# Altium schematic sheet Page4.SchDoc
size 431 x 279 mm; Date: Not shown in title block; ApprovedBy: Not shown in title block; CheckedBy: Not shown in title block; Author: Not shown in title block; CompanyName: Not shown in title block; Engineer: Not shown in title block; Organization: Not shown in title block; Address1: Not shown in title block; Address2: Not shown in title block; Address3: Not shown in title block; Address4: Not shown in title block; DocumentNumber: 5; Revision: Use project parameter SCH_Rev; SheetNumber: 5; SheetTotal: 5; PageSetup: Record=PageOptions|CenterHorizontal=True|CenterVertical=True|PrintScale=1.00|XCorrection=1.00|YCorrection=1.00|PrintKind=0|BorderSize=5000000|LeftOffset=0|BottomOffset=0|Orientation=2|PaperLength=1000|PaperWidth=1000|Scale=100|PaperSource=15|PrintQuality=600|MediaType=1|DitherType=10|PaperKind=Letter|PrintScaleMode=1
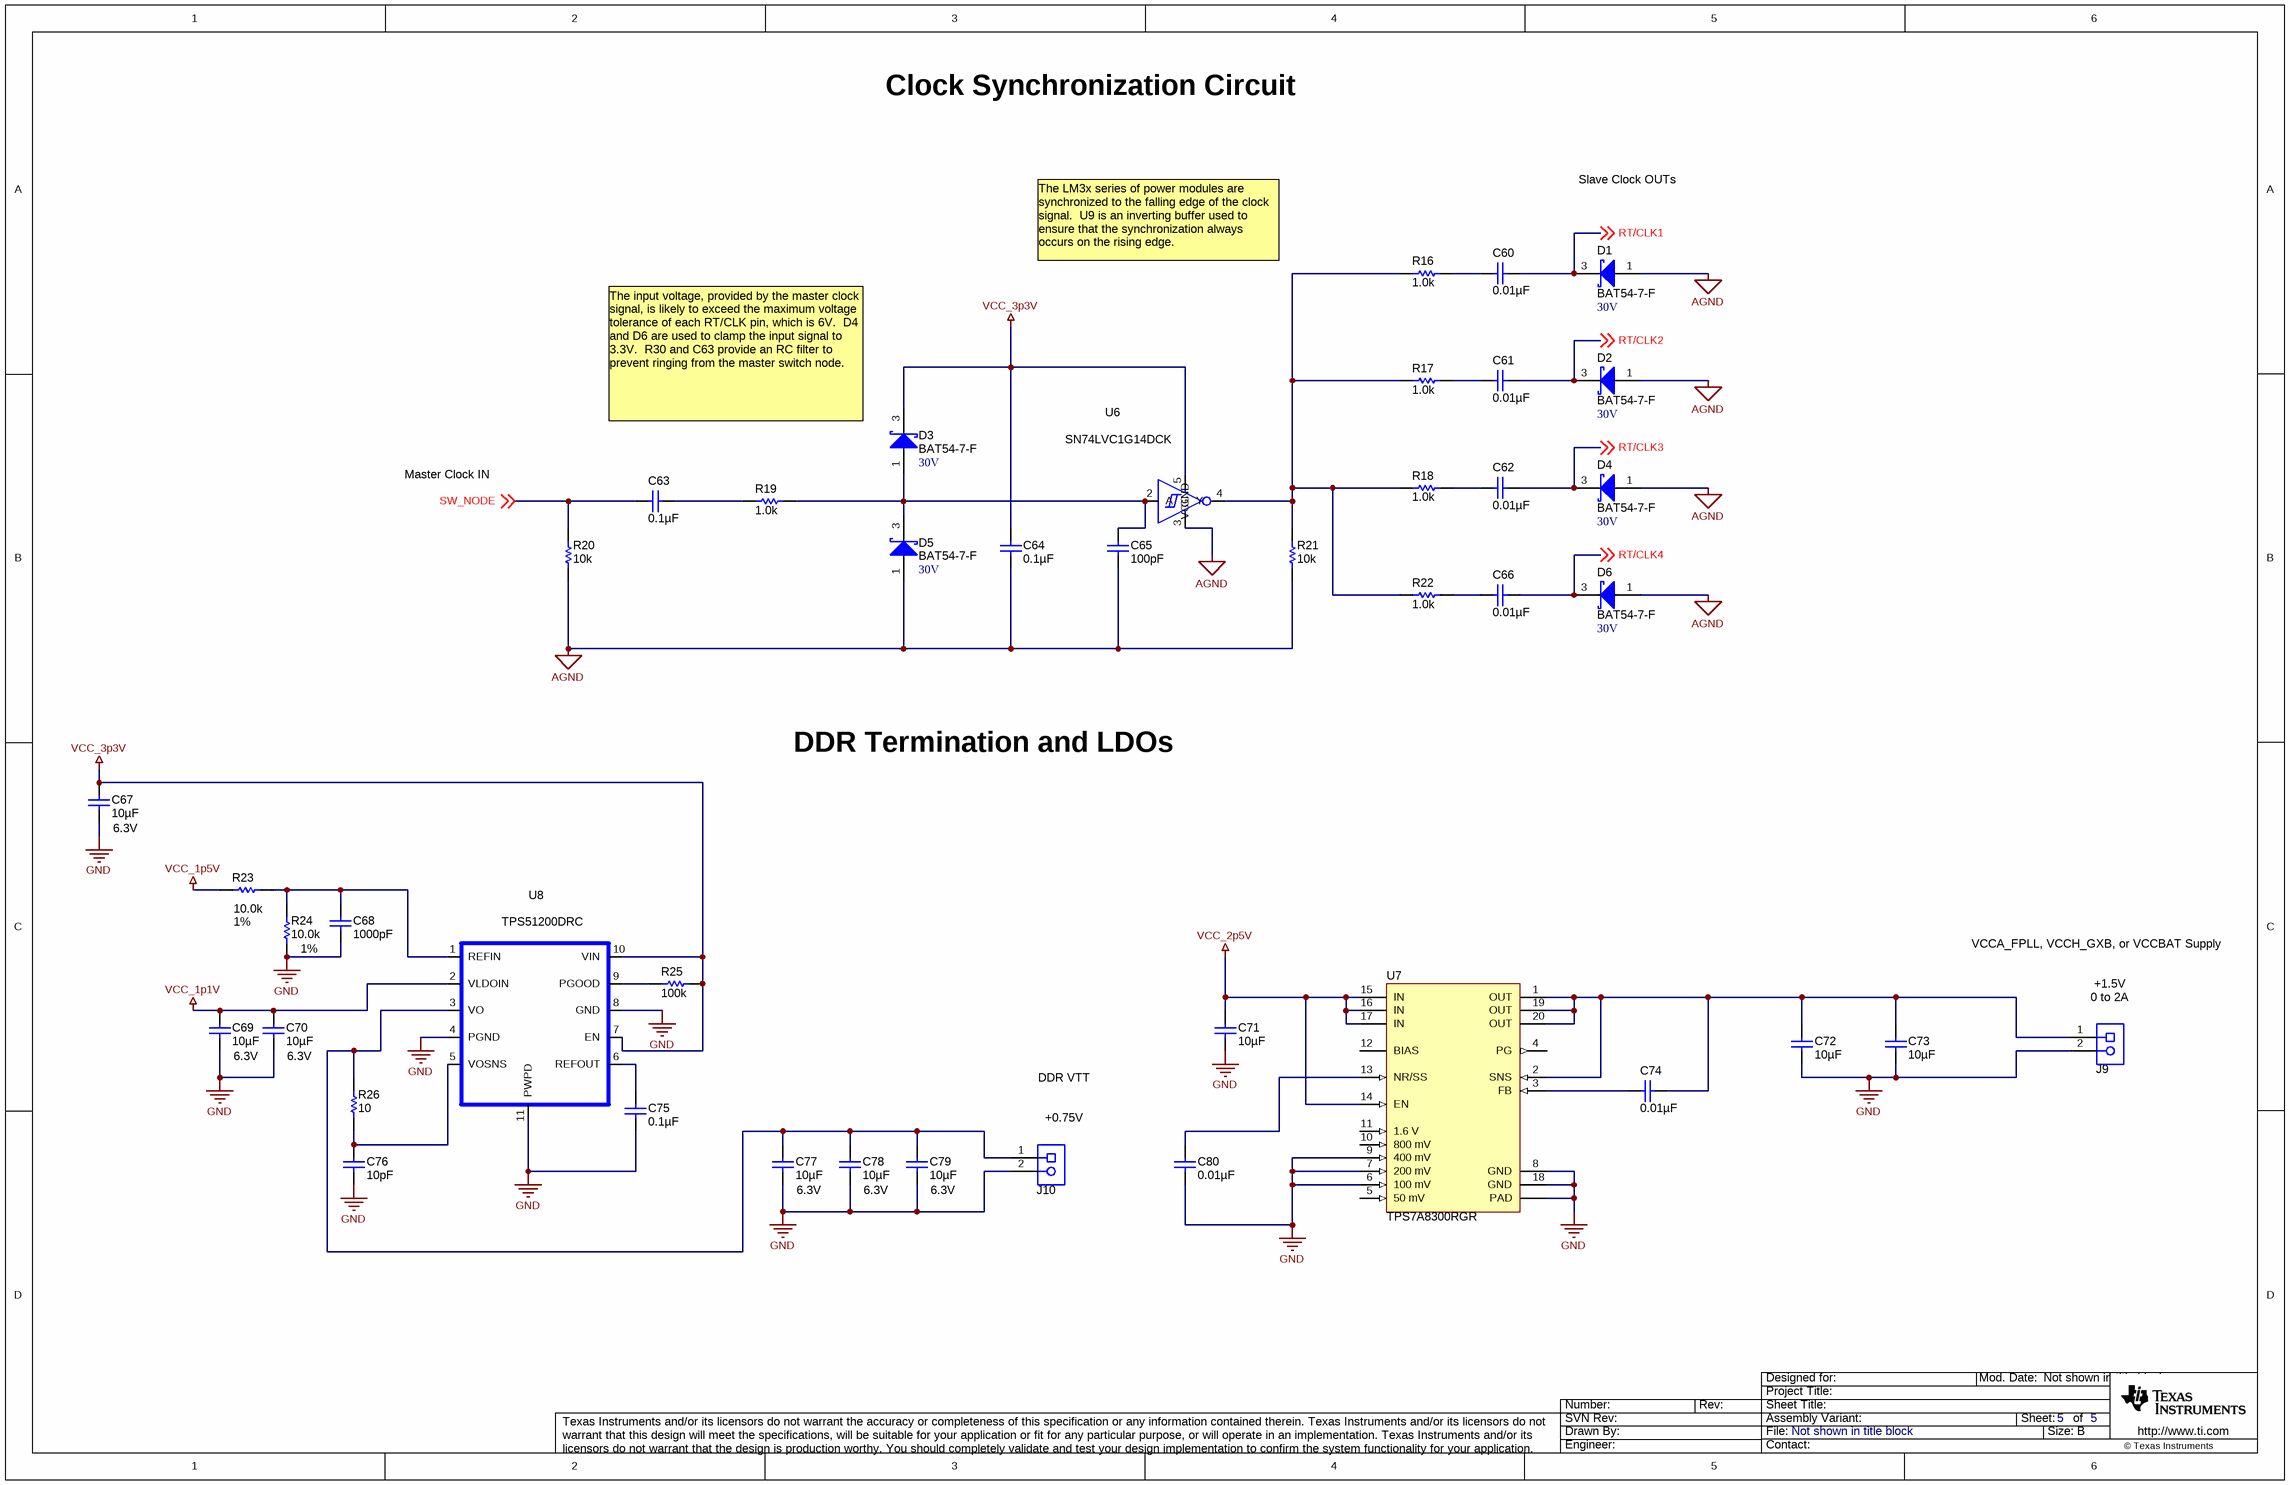
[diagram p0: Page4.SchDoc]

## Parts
C60  ValueDisplayed: 0.01µF  [0603]  (hidden comment: C0603C103J5RACTU)
C61  ValueDisplayed: 0.01µF  [0603]  (hidden comment: C0603C103J5RACTU)
C62  ValueDisplayed: 0.01µF  [0603]  (hidden comment: C0603C103J5RACTU)
C63  ValueDisplayed: 0.1µF  [0603]  (hidden comment: GCM188R71H104KA57B)
C64  ValueDisplayed: 0.1µF  [0603]  (hidden comment: GCM188R71H104KA57B)
C65  ValueDisplayed: 100pF  [0603]  (hidden comment: 06035A101JAT2A)
C66  ValueDisplayed: 0.01µF  [0603]  (hidden comment: C0603C103J5RACTU)
C67  ValueDisplayed: 10µF  Value2: 6.3V  [0603]  (hidden comment: C0603C106M9PACTU)
C68  ValueDisplayed: 1000pF  [0603]  (hidden comment: 06031C102JAT2A)
C69  ValueDisplayed: 10µF  Value2: 6.3V  [0603]  (hidden comment: C0603C106M9PACTU)
C70  ValueDisplayed: 10µF  Value2: 6.3V  [0603]  (hidden comment: C0603C106M9PACTU)
C71  ValueDisplayed: 10µF  [0805_HV]  (hidden comment: GRM21BR61A106KE19L)
C72  ValueDisplayed: 10µF  [0805_HV]  (hidden comment: GRM21BR61A106KE19L)
C73  ValueDisplayed: 10µF  [0805_HV]  (hidden comment: GRM21BR61A106KE19L)
C74  ValueDisplayed: 0.01µF  [0603]  (hidden comment: C0603C103J5RACTU)
C75  ValueDisplayed: 0.1µF  [0603]  (hidden comment: GCM188R71H104KA57B)
C76  ValueDisplayed: 10pF  [0603]  (hidden comment: 06035A100JAT2A)
C77  ValueDisplayed: 10µF  Value2: 6.3V  [0603]  (hidden comment: C0603C106M9PACTU)
C78  ValueDisplayed: 10µF  Value2: 6.3V  [0603]  (hidden comment: C0603C106M9PACTU)
C79  ValueDisplayed: 10µF  Value2: 6.3V  [0603]  (hidden comment: C0603C106M9PACTU)
C80  ValueDisplayed: 0.01µF  [0603]  (hidden comment: C0603C103J5RACTU)
D1  BAT54-7-F  value 30V  [SOT-23]
D2  BAT54-7-F  value 30V  [SOT-23]
D3  BAT54-7-F  value 30V  [SOT-23]
D4  BAT54-7-F  value 30V  [SOT-23]
D5  BAT54-7-F  value 30V  [SOT-23]
D6  BAT54-7-F  value 30V  [SOT-23]
J9  ED120/2DS  [CONN_ED120-2DS]  (value not drawn)
J10  ED120/2DS  [CONN_ED120-2DS]  (value not drawn)
R16  value 1.0k  [0603]  (hidden comment: CRCW06031K00JNEA)
R17  value 1.0k  [0603]  (hidden comment: CRCW06031K00JNEA)
R18  value 1.0k  [0603]  (hidden comment: CRCW06031K00JNEA)
R19  value 1.0k  [0603]  (hidden comment: CRCW06031K00JNEA)
R20  value 10k  [0603]  (hidden comment: CRCW060310K0JNEA)
R21  value 10k  [0603]  (hidden comment: CRCW060310K0JNEA)
R22  value 1.0k  [0603]  (hidden comment: CRCW06031K00JNEA)
R23  value 10.0k  Value1: 1%  [0603]  (hidden comment: CRCW060310K0FKEA)
R24  value 10.0k  Value1: 1%  [0603]  (hidden comment: CRCW060310K0FKEA)
R25  value 100k  [0603]  (hidden comment: CRCW0603100KFKEA)
R26  value 10  [0603]  (hidden comment: CRCW060310R0JNEA)
U6  SN74LVC1G14DCK  [SOP_5P.65MM(DCK)]
U7  TPS7A8300RGR  [RGR0020A]
U8  TPS51200DRC  [DRC-10PA]

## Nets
AGND: C64.1 C65.2 D1.1(A) D2.1(A) D4.1(A) D5.1(A) D6.1(A) R20.1 R21.1 U6.3(GND)
GND: C67.1 C68.1 C69.1 C70.1 C71.2 C72.2 C73.2 C75.1 C76.1 C77.1 C78.1 C79.1 C80.1 J9.2 J10.2 R24.1 U7.6(100_mV) U7.7(200_mV) U7.8(GND) U7.9(400_mV) U7.18(GND) U7.21(PAD) U8.4(PGND) U8.8(GND) U8.11(PWPD)
VCC_1p1V: C69.2 C70.2 U8.2(VLDOIN)
VCC_1p5V: R23.2
VCC_2p5V: C71.1 U7.14(EN) U7.15(IN) U7.16(IN) U7.17(IN)
VCC_3p3V: C64.2 C67.2 D3.3(K) R25.1 U6.5(VCC) U8.7(EN) U8.10(VIN)
RT/CLK1: C60.2 D1.3(K) ; off-sheet RT/CLK1
RT/CLK2: C61.2 D2.3(K) ; off-sheet RT/CLK2
RT/CLK3: C62.2 D4.3(K) ; off-sheet RT/CLK3
RT/CLK4: C66.2 D6.3(K) ; off-sheet RT/CLK4
SW_NODE: C63.1 R20.2 ; off-sheet SW_NODE
NetC60_1: C60.1 R16.1
NetC61_1: C61.1 R17.1
NetC62_1: C62.1 R18.1
NetC63_2: C63.2 R19.2
NetC65_1: C65.1 D3.1(A) D5.3(K) R19.1 U6.2(A)
NetC66_1: C66.1 R22.1
NetC68_2: C68.2 R23.1 R24.2 U8.1(REFIN)
NetC72_1: C72.1 C73.1 C74.2 J9.1 U7.1(OUT) U7.2(SNS) U7.19(OUT) U7.20(OUT)
NetC74_1: C74.1 U7.3(FB)
NetC75_2: C75.2 U8.6(REFOUT)
NetC76_2: C76.2 R26.1 U8.5(VOSNS)
NetC77_2: C77.2 C78.2 C79.2 J10.1 R26.2 U8.3(VO)
NetC80_2: C80.2 U7.13(NR/SS)
NetR16_2: R16.2 R17.2 R18.2 R21.2 R22.2 U6.4(Y)
NetR25_2: R25.2 U8.9(PGOOD)

Not connected (* = marked no-connect by the designer): U7 4(PG) 5(50_mV) 10(800_mV) 11(1.6_V) 12(BIAS)

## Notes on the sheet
- Clock Synchronization Circuit
- Slave Clock OUTs
- The LM3x series of power modules are synchronized to the falling edge of the clock signal.  U9 is an inverting buffer used to ensure that the synchronization always occurs on the rising edge.
- (near D3) The input voltage, provided by the master clock signal, is likely to exceed the maximum voltage tolerance of each RT/CLK pin, which is 6V.  D4 and D6 are used to clamp the input signal to 3.3V.  R30 and C63 provide an RC filter to prevent ringing from the master switch node.
- Master Clock IN
- DDR Termination and LDOs
- VCCA_FPLL, VCCH_GXB, or VCCBAT Supply
- (near J9) +1.5V
- (near J9) 0 to 2A
- DDR VTT
- (near J10) +0.75V

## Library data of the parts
C60-C62 C66 C74 C80 = C0603C103J5RACTU: CAP, CERM, 0.01uF, 50V, +/-5%, X7R, 0603; Manufacturer: Kemet; Polarized: N; CompType: Capacitor; U/M: EA; Cap_F: 0.00000001; Tolerance_%: 5; Value1: Unknown; VDC_V: 50; TaMin_C: -55; TaMax_C: 125
C63 C64 C75 = GCM188R71H104KA57B: CAP, CERM, 0.1uF, 50V, +/-10%, X7R, 0603; Manufacturer: MuRata; Polarized: N; CompType: Capacitor; U/M: EA; Cap_F: 0.0000001; Tolerance_%: 10; ESR_Ohm: 0.02; Value1: 0.02 ohm; VDC_V: 50; IRMS_A: 1.84; TaMin_C: -55; TaMax_C: 125
C65 = 06035A101JAT2A: CAP, CERM, 100pF, 50V, +/-5%, C0G/NP0, 0603; Manufacturer: AVX; Polarized: N; CompType: Capacitor; U/M: EA; Cap_F: 0.0000000001; Tolerance_%: 5; ESR_Ohm: 0.119; Value1: 0.119 ohm; VDC_V: 50; TaMin_C: -55; TaMax_C: 125
C67 C69 C70 C77-C79 = C0603C106M9PACTU: CAP, CERM, 10uF, 6.3V, +/-20%, X5R, 0603; Manufacturer: Kemet; Polarized: N; CompType: Capacitor; U/M: EA; Cap_F: 0.00001; Tolerance_%: 20; ESR_Ohm: 0.004; Value1: 0.004 ohm; VDC_V: 6.3; IRMS_A: 8.9; TaMin_C: -55; TaMax_C: 85
C68 = 06031C102JAT2A: CAP, CERM, 1000pF, 100V, +/-5%, X7R, 0603; Manufacturer: AVX; Polarized: N; CompType: Capacitor; U/M: EA; Cap_F: 0.000000001; Tolerance_%: 5; ESR_Ohm: 0.276; Value1: 0.276 ohm; VDC_V: 100; TaMin_C: -55; TaMax_C: 125
C71-C73 = GRM21BR61A106KE19L: CAP, CERM, 10uF, 10V, +/-10%, X5R, 0805; Manufacturer: MuRata; Polarized: N; CompType: Capacitor; U/M: EA; Cap_F: 0.00001; Tolerance_%: 10; ESR_Ohm: 0.002; Value1: 0.002 ohm; TaMin_C: -55; TaMax_C: 85; Cap_Case: 0805
C76 = 06035A100JAT2A: CAP, CERM, 10pF, 50V, +/-5%, C0G/NP0, 0603; Manufacturer: AVX; Polarized: N; CompType: Capacitor; U/M: EA; Cap_F: 0.00000000001; Tolerance_%: 5; ESR_Ohm: 0.403; Value1: 0.403 ohm; VDC_V: 50; TaMin_C: -55; TaMax_C: 125
D1-D6 = BAT54-7-F: Diode, Schottky, 30V, 0.2A, SOT-23; Manufacturer: Diodes Inc.; U/M: EA; Vf_V: 0.65; Value2: 0.65V; Io_A: 0.2; Vr_V: 30; TJmax_C: 125
J9 J10 = ED120/2DS: TERMINAL BLOCK 5.08MM VERT 2POS, TH; Manufacturer: On-Shore Technology; SymbolCreator: a0412235; U/M: EA
R16-R19 R22 = CRCW06031K00JNEA: RES, 1.0k ohm, 5%, 0.1W, 0603; Manufacturer: Vishay-Dale; CompType: Resistor; Res_ohm: 1000; Value_Code: 1k00; Tolerance_%: 5; Power_W: 0.1; VDC_V: 75; TempCo: 200 ppm/C; EIA_Code: E24; U/M: EA
R20 R21 = CRCW060310K0JNEA: RES, 10k ohm, 5%, 0.1W, 0603; Manufacturer: Vishay-Dale; CompType: Resistor; Res_ohm: 10000; Value_Code: 10k0; Tolerance_%: 5; Power_W: 0.1; VDC_V: 75; TempCo: 200 ppm/C; EIA_Code: E24; U/M: EA
R23 R24 = CRCW060310K0FKEA: RES, 10.0k ohm, 1%, 0.1W, 0603; Manufacturer: Vishay-Dale; CompType: Resistor; Res_ohm: 10000; Value_Code: 10k0; Tolerance_%: 1; Power_W: 0.1; VDC_V: 75; TempCo: 100 ppm/C; EIA_Code: E96; U/M: EA
R25 = CRCW0603100KFKEA: RES, 100k ohm, 1%, 0.1W, 0603; Manufacturer: Vishay-Dale; CompType: Resistor; Res_ohm: 100000; Tolerance_%: 1; Power_W: 0.1; VDC_V: 75; TempCo: 100 ppm/C; EIA_Code: E96; U/M: EA
R26 = CRCW060310R0JNEA: RES, 10 ohm, 5%, 0.1W, 0603; Manufacturer: Vishay-Dale; CompType: Resistor; Value_Code: 10R0; Tolerance_%: 5; Power_W: 0.1; VDC_V: 75; TempCo: 200 ppm/C; EIA_Code: E24; U/M: EA
U6 = SN74LVC1G14DCK: IC, Single Schmitt-Trigger Inverter; Manufacturer: TI; Alternate Manufacturer: None; Area: 19,500
U7 = TPS7A8300RGR: 2-A, 6-µVRMS, RF, LDO Voltage Regulator, RGR0020A; Alternate Manufacturer: None; Manufacturer: Texas Instruments; SymbolCreator: a0411947; CompType: IC; U/M: EA
U8 = TPS51200DRC: IC, Sink/Source DDR Termination Regulator; Manufacturer: TI; Alternate Manufacturer: None; Area: 30400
